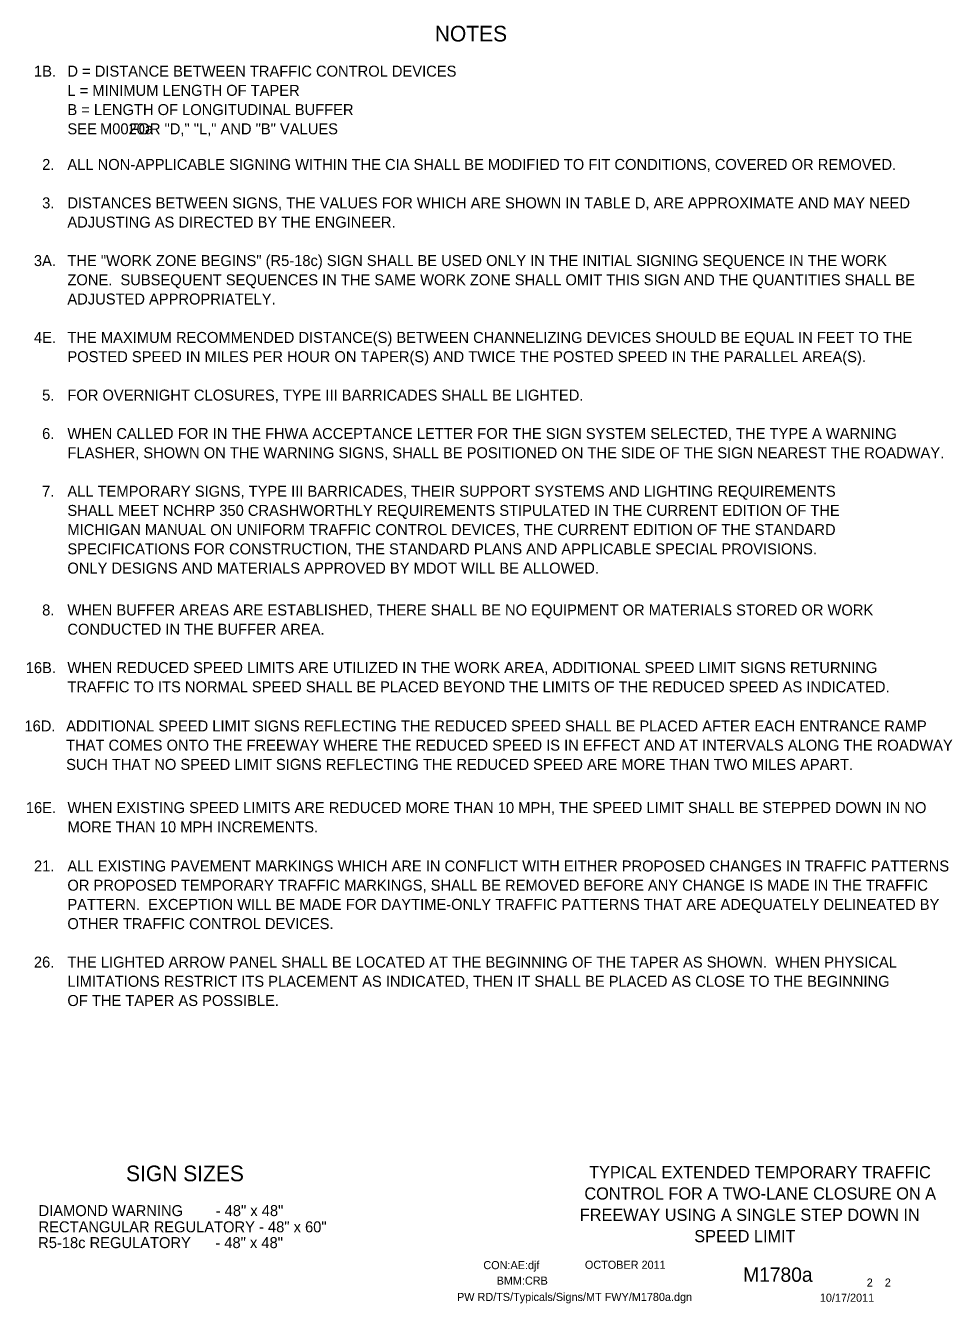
# Model space of a CAD drawing. Extents: x 16553 to 18478, y 5759 to 7026.
# Drawn here: x 17770 to 18478, y 5932 to 6909 of the extents above; entities that cross this region are included whole.
import ezdxf

# ---------------------------------------------------------------- set-up
doc = ezdxf.new("R2010")
doc.units = 0
for name, color, linetype in [('BORDER', 7, 'Continuous'), ('BORDER_SIGNAL_WO', 7, 'Continuous'), ('TYPICAL_TEXT_DIMEN_PR', 7, 'Continuous')]:
    doc.layers.add(name, color=color, linetype=linetype)

msp = doc.modelspace()

# ---------------------------------------------------------------- linework, layer by layer
at = {"layer": 'BORDER'}
msp.add_line((17909.25, 6035.02), (17909.25, 6035.02), dxfattribs=at)

# ---------------------------------------------------------------- texts
for s, p in [('TYPICAL EXTENDED TEMPORARY TRAFFIC', (18200.54, 6027.6)), ('CONTROL FOR A TWO-LANE CLOSURE ON A', (18196.92, 6011.3)), ('FREEWAY USING A SINGLE STEP DOWN IN ', (18193.42, 5995)), ('SPEED LIMIT', (18280.92, 5978.7))]:
    msp.add_text(s, height=9.3, dxfattribs=at).set_placement(p)
at = {"layer": 'BORDER_SIGNAL_WO'}
for s, height, p in [('CON:AE:djf  ', 6.2, (18119.69, 5958.06)), ('    OCTOBER 2011', 6.2, (18188.08, 5958.34)), ('BMM:CRB', 6.2, (18129.81, 5946.17)), ('    M1780a   ', 11, (18301.86, 5948.38)), (' 2    2 ', 6.2, (18410.45, 5944.7)), ('PW RD/TS/Typicals/Signs/MT FWY/M1780a.dgn      ', 6.2, (18099.55, 5933.71)), ('10/17/2011', 6.2, (18376.93, 5933.13))]:
    msp.add_text(s, height=height, dxfattribs=at).set_placement(p)
at = {"layer": 'TYPICAL_TEXT_DIMEN_PR'}
for s, height, p in [('NOTES', 12, (18082.55, 6897)), ('1B.', 8.4, (17776.19, 6870.11)), ('D = DISTANCE BETWEEN TRAFFIC CONTROL DEVICES', 8.4, (17801.7, 6870.11)), ('L = MINIMUM LENGTH OF TAPER', 8.4, (17801.7, 6855.41)), ('B = LENGTH OF LONGITUDINAL BUFFER', 8.4, (17801.7, 6840.71)), ('SEE        FOR "D," "L," AND "B" VALUES', 8.4, (17801.7, 6826.01)), ('M0020a', 8.4, (17826.62, 6826.01)), ('2.', 8.4, (17782.39, 6798.75)), ('ALL NON-APPLICABLE SIGNING WITHIN THE CIA SHALL BE MODIFIED TO FIT CONDITIONS, COVERED OR REMOVED.', 8.4, (17801.7, 6798.75)), ('3.', 8.4, (17782.39, 6769.35)), ('DISTANCES BETWEEN SIGNS, THE VALUES FOR WHICH ARE SHOWN IN TABLE D, ARE APPROXIMATE AND MAY NEED', 8.4, (17801.7, 6769.35)), ('ADJUSTING AS DIRECTED BY THE ENGINEER.', 8.4, (17801.7, 6754.65)), ('THE "WORK ZONE BEGINS" (R5-18c) SIGN SHALL BE USED ONLY IN THE INITIAL SIGNING SEQUENCE IN THE WORK', 8.4, (17801.7, 6725.24)), ('3A.', 8.4, (17776.09, 6725.24)), ('ZONE.  SUBSEQUENT SEQUENCES IN THE SAME WORK ZONE SHALL OMIT THIS SIGN AND THE QUANTITIES SHALL BE', 8.4, (17801.7, 6710.54)), ('ADJUSTED APPROPRIATELY.', 8.4, (17801.7, 6695.84)), ('THE MAXIMUM RECOMMENDED DISTANCE(S) BETWEEN CHANNELIZING DEVICES SHOULD BE EQUAL IN FEET TO THE', 8.4, (17801.7, 6666.45)), ('4E.', 8.4, (17776.13, 6666.45)), ('POSTED SPEED IN MILES PER HOUR ON TAPER(S) AND TWICE THE POSTED SPEED IN THE PARALLEL AREA(S).', 8.4, (17801.7, 6651.75)), ('5.', 8.4, (17782.39, 6622.35)), ('FOR OVERNIGHT CLOSURES, TYPE III BARRICADES SHALL BE LIGHTED.', 8.4, (17801.7, 6622.35)), ('6.', 8.4, (17782.34, 6592.95)), ('WHEN CALLED FOR IN THE FHWA ACCEPTANCE LETTER FOR THE SIGN SYSTEM SELECTED, THE TYPE A WARNING ', 8.4, (17801.7, 6592.95)), ('FLASHER, SHOWN ON THE WARNING SIGNS, SHALL BE POSITIONED ON THE SIDE OF THE SIGN NEAREST THE ROADWAY.', 8.4, (17801.7, 6578.25)), ('7.', 8.4, (17782.34, 6548.82)), ('ALL TEMPORARY SIGNS, TYPE III BARRICADES, THEIR SUPPORT SYSTEMS AND LIGHTING REQUIREMENTS', 8.4, (17801.7, 6548.84)), ('SHALL MEET NCHRP 350 CRASHWORTHLY REQUIREMENTS STIPULATED IN THE CURRENT EDITION OF THE', 8.4, (17801.7, 6534.14)), ('MICHIGAN MANUAL ON UNIFORM TRAFFIC CONTROL DEVICES, THE CURRENT EDITION OF THE STANDARD', 8.4, (17801.7, 6519.44)), ('SPECIFICATIONS FOR CONSTRUCTION, THE STANDARD PLANS AND APPLICABLE SPECIAL PROVISIONS.', 8.4, (17801.7, 6504.74)), ('ONLY DESIGNS AND MATERIALS APPROVED BY MDOT WILL BE ALLOWED.', 8.4, (17801.7, 6490.04)), ('8.', 8.4, (17782.39, 6458)), ('WHEN BUFFER AREAS ARE ESTABLISHED, THERE SHALL BE NO EQUIPMENT OR MATERIALS STORED OR WORK     ', 8.4, (17801.7, 6458)), ('CONDUCTED IN THE BUFFER AREA.', 8.4, (17801.7, 6443.3)), ('16B.', 8.4, (17769.84, 6413.9)), ('WHEN REDUCED SPEED LIMITS ARE UTILIZED IN THE WORK AREA, ADDITIONAL SPEED LIMIT SIGNS RETURNING', 8.4, (17801.7, 6413.96)), ('TRAFFIC TO ITS NORMAL SPEED SHALL BE PLACED BEYOND THE LIMITS OF THE REDUCED SPEED AS INDICATED.', 8.4, (17801.7, 6399.26)), ('16D.', 8.4, (17768.86, 6369.31)), ('ADDITIONAL SPEED LIMIT SIGNS REFLECTING THE REDUCED SPEED SHALL BE PLACED AFTER EACH ENTRANCE RAMP', 8.4, (17800.73, 6369.31)), ('THAT COMES ONTO THE FREEWAY WHERE THE REDUCED SPEED IS IN EFFECT AND AT INTERVALS ALONG THE ROADWAY', 8.4, (17800.73, 6354.61)), ('SUCH THAT NO SPEED LIMIT SIGNS REFLECTING THE REDUCED SPEED ARE MORE THAN TWO MILES APART.', 8.4, (17800.73, 6339.91)), ('16E.', 8.4, (17769.92, 6306.86)), ('WHEN EXISTING SPEED LIMITS ARE REDUCED MORE THAN 10 MPH, THE SPEED LIMIT SHALL BE STEPPED DOWN IN NO', 8.4, (17801.79, 6306.86)), ('MORE THAN 10 MPH INCREMENTS.', 8.4, (17801.79, 6292.16)), ('21.', 8.4, (17776.14, 6262.21)), ('ALL EXISTING PAVEMENT MARKINGS WHICH ARE IN CONFLICT WITH EITHER PROPOSED CHANGES IN TRAFFIC PATTERNS', 8.4, (17801.7, 6262.21)), ('OR PROPOSED TEMPORARY TRAFFIC MARKINGS, SHALL BE REMOVED BEFORE ANY CHANGE IS MADE IN THE TRAFFIC', 8.4, (17801.7, 6247.51)), ('PATTERN.  EXCEPTION WILL BE MADE FOR DAYTIME-ONLY TRAFFIC PATTERNS THAT ARE ADEQUATELY DELINEATED BY', 8.4, (17801.7, 6232.81)), ('OTHER TRAFFIC CONTROL DEVICES.', 8.4, (17801.7, 6218.11)), ('26.', 8.4, (17776.09, 6188.71)), ('THE LIGHTED ARROW PANEL SHALL BE LOCATED AT THE BEGINNING OF THE TAPER AS SHOWN.  WHEN PHYSICAL', 8.4, (17801.7, 6188.71)), ('LIMITATIONS RESTRICT ITS PLACEMENT AS INDICATED, THEN IT SHALL BE PLACED AS CLOSE TO THE BEGINNING', 8.4, (17801.7, 6174.01)), ('OF THE TAPER AS POSSIBLE.', 8.4, (17801.7, 6159.31)), ('SIGN SIZES', 12, (17846.54, 6025.28)), ('DIAMOND WARNING        - 48" x 48"', 8.4, (17779.65, 5998.62)), ('RECTANGULAR REGULATORY - 48" x 60"', 8.4, (17779.65, 5986.22)), ('R5-18c REGULATORY      - 48" x 48"', 8.4, (17779.34, 5974.14))]:
    msp.add_text(s, height=height, dxfattribs=at).set_placement(p)

doc.saveas('drawing.dxf')
